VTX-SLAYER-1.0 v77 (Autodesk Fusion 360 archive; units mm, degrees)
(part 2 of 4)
sketch "Skizze49" plane through (0, 0, 7) normal (0, 0, 1) x axis (-1, 0, 0)
  curve K1 (-34.4729, 47.5027) -> (-34.8613, 50.4161)
  line L1 (-32.7992, 19.5622) -> (-34.4732, 21.3854)
  line L2 (21.7601, 20.324) -> (21.0607, 19.5622)
  curve K2 (14.991, 38.4401) -> (21.2218, 28.4813)
  curve K3 (14.991, 41.5582) -> (21.2218, 51.5169)
  line L3 (21.0607, 60.4361) -> (21.7601, 59.6743)
  line L4 (-34.4732, 58.6128) -> (-32.7992, 60.4361)
  line L5 (-23.7522, 44.4991) -> (-30.319, 44.4991)
  line L6 (-30.319, 41.4991) -> (-23.7522, 41.4991)
  line L7 (-23.7522, 38.4991) -> (-30.319, 38.4991)
  line L8 (-30.319, 35.4991) -> (-23.7522, 35.4991)
  curve K4 (-21.4163, 20.9358) -> (-22.7131, 20.0338)
  curve K5 (-21.4163, 59.0625) -> (-22.7131, 59.9644)
  curve K6 (23.3399, 24.4614) -> (21.2218, 28.4813)
  curve K7 (21.2218, 51.5169) -> (23.3399, 55.5369)
  line L9 (-26.3392, 32.4991) -> (-30.319, 32.4991)
  line L10 (-30.319, 29.4991) -> (-26.3392, 29.4991)
  curve K8 (-34.4732, 21.3854) -> (-34.8613, 29.5821)
  curve K9 (-34.8613, 50.4161) -> (-34.4732, 58.6128)
  curve K10 (-34.2161, 44.4991) -> (-34.4729, 47.5027)
  curve K11 (-34.0692, 39.9991) -> (-34.0919, 41.4991)
  curve K12 (-34.0919, 38.4991) -> (-34.0692, 39.9991)
  curve K13 (-34.0919, 38.4991) -> (-34.2161, 35.4991)
  curve K14 (-34.4729, 32.4955) -> (-34.2161, 35.4991)
  line L11 (-26.3392, 50.4991) -> (-30.319, 50.4991)
  line L12 (-30.319, 47.4991) -> (-26.3392, 47.4991)
  curve K15 (-5.8693, 25.0204) -> (1.6863, 24.3869)
  curve K16 (-5.8693, 54.9778) -> (1.6863, 55.6114)
  curve K17 (-32.7992, 19.5622) -> (-25.5215, 18.3445)
  curve K18 (-22.7131, 20.0338) -> (-25.5215, 18.3445)
  curve K19 (-5.8693, 25.0204) -> (-13.4249, 24.3869)
  curve K20 (10.9746, 20.0338) -> (13.7829, 18.3445)
  curve K21 (13.7829, 18.3445) -> (21.0607, 19.5622)
  curve K22 (14.9178, 39.9991) -> (14.991, 38.4401)
  curve K23 (14.9178, 39.9991) -> (14.991, 41.5582)
  curve K24 (13.7829, 61.6537) -> (21.0607, 60.4361)
  curve K25 (10.9746, 59.9644) -> (13.7829, 61.6537)
  curve K26 (-5.8693, 54.9778) -> (-13.4249, 55.6114)
  curve K27 (-22.7131, 59.9644) -> (-25.5215, 61.6537)
  curve K28 (-32.7992, 60.4361) -> (-25.5215, 61.6537)
  curve K29 (-34.0919, 41.4991) -> (-34.2161, 44.4991)
  curve K30 (-21.2077, 21.0728) -> (-21.4163, 20.9358)
  curve K31 (-13.5094, 24.37) -> (-21.2077, 21.0728)
  curve K32 (-13.4249, 24.3869) -> (-13.5094, 24.37)
  curve K33 (1.6863, 24.3869) -> (1.7709, 24.37)
  curve K34 (9.4692, 21.0728) -> (1.7709, 24.37)
  curve K35 (9.4692, 21.0728) -> (9.6778, 20.9358)
  curve K36 (9.6778, 20.9358) -> (10.9746, 20.0338)
  curve K37 (9.6778, 59.0625) -> (10.9746, 59.9644)
  curve K38 (9.4692, 58.9255) -> (9.6778, 59.0625)
  curve K39 (1.7709, 55.6283) -> (9.4692, 58.9255)
  curve K40 (1.6863, 55.6114) -> (1.7709, 55.6283)
  curve K41 (-13.4249, 55.6114) -> (-13.5094, 55.6283)
  curve K42 (-21.2077, 58.9255) -> (-13.5094, 55.6283)
  curve K43 (-21.2077, 58.9255) -> (-21.4163, 59.0625)
  curve K44 (-34.4729, 32.4955) -> (-34.8613, 29.5821)
  circle C1 centre (4.1749, 29.9966) radius 1.05
  circle C2 centre (-15.8251, 49.9966) radius 1.05
  circle C3 centre (-15.8251, 29.9966) radius 1.05
  circle C4 centre (4.1749, 49.9966) radius 1.05
  circle C5 centre (18.1718, 23.4983) radius 2
  circle C6 centre (-29.8282, 23.4983) radius 2
  circle C7 centre (18.1718, 56.4983) radius 2
  circle C8 centre (-29.8282, 56.4983) radius 2
  circle C9 centre (-15.8251, 49.9966) radius 2.1
  circle C10 centre (-15.8251, 29.9966) radius 2.1
  circle C11 centre (4.1749, 29.9966) radius 2.1
  circle C12 centre (4.1749, 49.9966) radius 2.1
  circle C13 centre (-5.8313, 39.9999) radius 2.625
  circle C14 centre (-15.8251, 49.9966) radius 1.05
  circle C15 centre (-15.8251, 29.9966) radius 1.05
  circle C16 centre (4.1749, 49.9966) radius 1.05
  circle C17 centre (4.1749, 29.9966) radius 1.05
  circle C18 centre (-15.8282, 29.9983) radius 2.1
  circle C19 centre (-15.8282, 49.9983) radius 2.1
  circle C20 centre (4.1718, 29.9983) radius 2.1
  circle C21 centre (-5.8282, 39.9983) radius 3
  circle C22 centre (4.1718, 49.9983) radius 2.1
  arc A1 centre (-23.7522, 42.9991) radius 1.5 clockwise from (-23.7522, 44.4991) to (-23.7522, 41.4991)
  arc A2 centre (-30.319, 42.9991) radius 1.5 clockwise from (-30.319, 41.4991) to (-30.319, 44.4991)
  arc A3 centre (-30.319, 36.9991) radius 1.5 clockwise from (-30.319, 35.4991) to (-30.319, 38.4991)
  arc A4 centre (-23.7522, 36.9991) radius 1.5 clockwise from (-23.7522, 38.4991) to (-23.7522, 35.4991)
  arc A5 centre (17.3404, 24.3819) radius 6 clockwise from (23.3399, 24.4614) to (21.7601, 20.324)
  arc A6 centre (17.3404, 55.6164) radius 6 clockwise from (21.7601, 59.6743) to (23.3399, 55.5369)
  arc A7 centre (-26.3392, 30.9991) radius 1.5 clockwise from (-26.3392, 32.4991) to (-26.3392, 29.4991)
  arc A8 centre (-30.319, 30.9991) radius 1.5 clockwise from (-30.319, 29.4991) to (-30.319, 32.4991)
  arc A9 centre (-30.319, 48.9991) radius 1.5 clockwise from (-30.319, 47.4991) to (-30.319, 50.4991)
  arc A10 centre (-26.3392, 48.9991) radius 1.5 clockwise from (-26.3392, 50.4991) to (-26.3392, 47.4991)
  circle C23 centre (-29.8693, 56.4991) radius 2.55
  circle C24 centre (18.1307, 56.4991) radius 2.55
  circle C25 centre (-29.8693, 23.4991) radius 2.55
  circle C26 centre (18.1307, 23.4991) radius 2.55
  circle C27 centre (-5.8693, 39.9991) radius 2.55
  circle C28 centre (-15.8693, 49.9991) radius 1.05
  circle C29 centre (4.1307, 49.9991) radius 1.05
  circle C30 centre (-15.8693, 29.9991) radius 1.05
  circle C31 centre (4.1307, 29.9991) radius 1.05
  dimension "d443" diameter C5 = 4
  dimension "d444" diameter C6 = 4 (= "d443")
  dimension "d445" diameter C7 = 4 (= "d443")
  dimension "d446" diameter C8 = 4 (= "d443")
work_plane "WorkPlane5" AlongDistance 25
sketch "Skizze50" plane through (0, 0, 32) normal (0, 0, 1) x axis (-1, 0, 0)
  line L1 (-34.2161, 35.4991) -> (-33.5931, 35.4991)
  line L2 (-34.2172, 44.4991) -> (-33.5931, 44.4991)
  line L3 (-26.4943, 39.9991) -> (14.9178, 39.9991)
  line L4 (34.1307, 43.8641) -> (34.1307, 36.1341)
  line L5 (21.0607, 19.5622) -> (32.5504, 32.0762)
  line L6 (-32.7992, 19.5622) -> (-33.4986, 20.324)
  line L7 (32.5504, 32.0762) -> (21.0607, 19.5622)
  line L8 (34.1307, 43.8641) -> (34.1307, 36.1341)
  line L9 (21.0607, 60.4361) -> (32.5504, 47.922)
  line L10 (-33.4986, 59.6743) -> (-32.7992, 60.4361)
  curve K1 (-34.4729, 47.5027) -> (-34.8613, 50.4161)
  line L11 (-32.7992, 19.5622) -> (-34.4732, 21.3854)
  line L12 (21.7601, 20.324) -> (21.0607, 19.5622)
  line L13 (21.0607, 60.4361) -> (21.7601, 59.6743)
  line L14 (-34.4732, 58.6128) -> (-32.7992, 60.4361)
  curve K2 (9.6778, 20.9358) -> (10.9746, 20.0338)
  curve K3 (9.6778, 59.0625) -> (10.9746, 59.9644)
  curve K4 (-21.4163, 20.9358) -> (-22.7131, 20.0338)
  curve K5 (-21.4163, 59.0625) -> (-22.7131, 59.9644)
  curve K6 (-35.0785, 55.5369) -> (-32.9603, 51.5169)
  curve K7 (-32.9603, 28.4813) -> (-35.0785, 24.4614)
  curve K8 (23.3399, 24.4614) -> (21.2218, 28.4813)
  curve K9 (21.2218, 51.5169) -> (23.3399, 55.5369)
  line L15 (-26.3392, 32.4991) -> (-30.319, 32.4991)
  line L16 (-30.319, 29.4991) -> (-26.3392, 29.4991)
  curve K10 (-34.4732, 21.3854) -> (-34.8613, 29.5821)
  curve K11 (-34.8613, 50.4161) -> (-34.4732, 58.6128)
  curve K12 (-34.2161, 44.4991) -> (-34.4729, 47.5027)
  curve K13 (-34.0919, 41.4991) -> (-34.2161, 44.4991)
  curve K14 (-34.0692, 39.9991) -> (-34.0919, 41.4991)
  curve K15 (-34.0919, 38.4991) -> (-34.0692, 39.9991)
  curve K16 (-34.0919, 38.4991) -> (-34.2161, 35.4991)
  curve K17 (-34.4729, 32.4955) -> (-34.2161, 35.4991)
  line L17 (-26.3392, 50.4991) -> (-30.319, 50.4991)
  line L18 (-30.319, 47.4991) -> (-26.3392, 47.4991)
  curve K18 (-5.8693, 54.9778) -> (1.6863, 55.6114)
  curve K19 (-5.8693, 54.9778) -> (-13.4249, 55.6114)
  curve K20 (-5.8693, 25.0204) -> (-13.4249, 24.3869)
  curve K21 (-5.8693, 25.0204) -> (1.6863, 24.3869)
  curve K22 (-5.8693, 25.0204) -> (1.6863, 24.3869)
  curve K23 (-5.8693, 54.9778) -> (1.6863, 55.6114)
  curve K24 (-25.5215, 18.3445) -> (-32.7992, 19.5622)
  curve K25 (-22.7131, 20.0338) -> (-25.5215, 18.3445)
  curve K26 (10.9746, 20.0338) -> (13.7829, 18.3445)
  curve K27 (21.0607, 19.5622) -> (13.7829, 18.3445)
  curve K28 (21.0607, 60.4361) -> (13.7829, 61.6537)
  curve K29 (10.9746, 59.9644) -> (13.7829, 61.6537)
  curve K30 (-22.7131, 59.9644) -> (-25.5215, 61.6537)
  curve K31 (-25.5215, 61.6537) -> (-32.7992, 60.4361)
  curve K32 (-32.7992, 19.5622) -> (-25.5215, 18.3445)
  curve K33 (-22.7131, 20.0338) -> (-25.5215, 18.3445)
  curve K34 (-5.8693, 25.0204) -> (-13.4249, 24.3869)
  curve K35 (10.9746, 20.0338) -> (13.7829, 18.3445)
  curve K36 (13.7829, 18.3445) -> (21.0607, 19.5622)
  curve K37 (13.7829, 61.6537) -> (21.0607, 60.4361)
  curve K38 (10.9746, 59.9644) -> (13.7829, 61.6537)
  curve K39 (-5.8693, 54.9778) -> (-13.4249, 55.6114)
  curve K40 (-22.7131, 59.9644) -> (-25.5215, 61.6537)
  curve K41 (-32.7992, 60.4361) -> (-25.5215, 61.6537)
  curve K42 (-21.4163, 20.9358) -> (-22.7131, 20.0338)
  curve K43 (-13.5094, 24.37) -> (-21.4163, 20.9358)
  curve K44 (-13.4249, 24.3869) -> (-13.5094, 24.37)
  curve K45 (1.6863, 24.3869) -> (1.7709, 24.37)
  curve K46 (1.7709, 24.37) -> (9.6778, 20.9358)
  curve K47 (1.7709, 55.6283) -> (9.6778, 59.0625)
  curve K48 (1.6863, 55.6114) -> (1.7709, 55.6283)
  curve K49 (-13.4249, 55.6114) -> (-13.5094, 55.6283)
  curve K50 (-13.5094, 55.6283) -> (-21.4163, 59.0625)
  curve K51 (-21.4163, 59.0625) -> (-22.7131, 59.9644)
  curve K52 (-21.2077, 21.0728) -> (-21.4163, 20.9358)
  curve K53 (-13.5094, 24.37) -> (-21.2077, 21.0728)
  curve K54 (-13.4249, 24.3869) -> (-13.5094, 24.37)
  curve K55 (1.6863, 24.3869) -> (1.7709, 24.37)
  curve K56 (9.4692, 21.0728) -> (1.7709, 24.37)
  curve K57 (9.4692, 21.0728) -> (9.6778, 20.9358)
  curve K58 (9.6778, 20.9358) -> (10.9746, 20.0338)
  curve K59 (9.6778, 59.0625) -> (10.9746, 59.9644)
  curve K60 (9.4692, 58.9255) -> (9.6778, 59.0625)
  curve K61 (1.7709, 55.6283) -> (9.4692, 58.9255)
  curve K62 (1.6863, 55.6114) -> (1.7709, 55.6283)
  curve K63 (-13.4249, 55.6114) -> (-13.5094, 55.6283)
  curve K64 (-21.2077, 58.9255) -> (-13.5094, 55.6283)
  curve K65 (-21.2077, 58.9255) -> (-21.4163, 59.0625)
  curve K66 (-34.4729, 32.4955) -> (-34.8613, 29.5821)
  line L19 (3.2014, 37.2064) -> (18.1307, 23.4991)
  line L20 (3.2014, 42.7918) -> (18.1307, 56.4991)
  line L21 (25.9, 31.9611) -> (18.1307, 23.4991)
  line L22 (25.9, 48.0372) -> (18.1307, 56.4991)
  line L23 (6.5519, 27.8311) -> (12.5889, 23.7993)
  line L24 (6.5519, 52.1671) -> (12.5889, 56.1989)
  line L25 (-12.7701, 29.0204) -> (1.0316, 29.0204)
  line L26 (-12.7701, 50.9778) -> (1.0316, 50.9778)
  line L27 (19.9777, 28.7328) -> (21.5825, 30.4807)
  line L28 (19.9777, 51.2654) -> (21.5825, 49.5175)
  line L29 (-26.1937, 36.9643) -> (-19.1192, 29.9733)
  line L30 (-26.1937, 39.9991) -> (-26.1937, 36.9643)
  line L31 (-26.1937, 43.034) -> (-19.1192, 50.025)
  line L32 (-26.1937, 39.9991) -> (-26.1937, 43.034)
  line L33 (39.4861, -5.3562) -> (4.1307, 29.9991)
  line L34 (54.1307, 29.9991) -> (4.1307, 29.9991)
  line L35 (-51.2246, -5.3562) -> (-15.8693, 29.9991)
  line L36 (34.1307, 29.9991) -> (-15.8693, 29.9991)
  line L37 (-5.7883, 39.9991) -> (4.1307, 29.9991)
  line L38 (-5.7883, 39.9991) -> (-15.8693, 29.9991)
  line L39 (39.4861, 85.3545) -> (4.1307, 49.9991)
  line L40 (-5.7883, 39.9991) -> (4.1307, 49.9991)
  line L41 (-5.7883, 39.9991) -> (-15.8693, 49.9991)
  line L42 (-51.2246, 85.3545) -> (-15.8693, 49.9991)
  line L43 (-2.5295, 39.9991) -> (4.166, 33.2489)
  line L44 (0.9769, 30.784) -> (-5.7883, 37.6045)
  line L45 (-13.4558, 29.9991) -> (-5.7883, 37.6045)
  line L46 (-15.8592, 33.2491) -> (-9.0541, 39.9991)
  line L47 (0.9769, 49.2142) -> (-5.7883, 42.3937)
  line L48 (-2.5295, 39.9991) -> (4.166, 46.7493)
  line L49 (-13.4558, 49.9991) -> (-5.7883, 42.3937)
  line L50 (-15.8592, 46.7491) -> (-9.0541, 39.9991)
  line L51 (14.9457, 39.9991) -> (6.7725, 31.8921)
  line L52 (7.6315, 27.1101) -> (18.0788, 37.4728)
  line L53 (7.6315, 52.8881) -> (18.0788, 42.5254)
  line L54 (14.9457, 39.9991) -> (6.7725, 48.1061)
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  point P2 (-33.5931, 39.9991)
  point P7 (-26.4943, 39.9991)
  point P94 (-34.2161, 35.4991)
  point P141 (-34.2161, 35.4991)
  point P56 (18.1307, 23.4991)
  point P142 (18.1307, 23.4991)
  point P144 (18.1307, 56.4991)
  point P143 (3.2014, 37.2064)
  point P145 (3.2014, 42.7918)
  point P147 (18.1307, 56.4991)
  point P146 (25.9, 31.9611)
  point P148 (25.9, 48.0372)
  point P6 (14.9178, 39.9991)
  point P39 (31.849, 39.9991)
  point P150 (18.1307, 23.4991)
  point P156 (12.5889, 23.7993)
  point P158 (12.5889, 56.1989)
  point P157 (6.5519, 27.8311)
  point P159 (6.5519, 52.1671)
  point P160 (1.0316, 29.0204)
  point P162 (1.0316, 50.9778)
  point P161 (-12.7701, 29.0204)
  point P163 (-12.7701, 50.9778)
  point P164 (21.5825, 30.4807)
  point P166 (21.5825, 49.5175)
  point P165 (19.9777, 28.7328)
  point P167 (19.9777, 51.2654)
  point P170 (-26.1937, 39.9991)
  point P168 (-19.1192, 29.9733)
  point P171 (-19.1192, 50.025)
  point P169 (-26.1937, 36.9643)
  point P172 (-26.1937, 43.034)
  point P173 (-26.1937, 39.9991)
  point P106 (4.1307, 29.9991)
  point P174 (4.1307, 29.9991)
  point P72 (-15.8693, 29.9991)
  point P177 (-15.8693, 29.9991)
  point P180 (-5.7883, 39.9991)
  point P181 (-15.8693, 29.9991)
  point P182 (4.1307, 49.9991)
  point P175 (39.4861, -5.3562)
  point P183 (39.4861, 85.3545)
  point P186 (-15.8693, 49.9991)
  point P178 (-51.2246, -5.3562)
  point P187 (-51.2246, 85.3545)
  point P184 (-5.7883, 39.9991)
  point P185 (-15.8693, 49.9991)
  point P189 (-2.5295, 39.9991)
  point P190 (-5.7883, 37.6045)
  point P192 (-13.4558, 29.9991)
  point P193 (-9.0541, 39.9991)
  point P188 (4.166, 33.2489)
  point P197 (4.166, 46.7493)
  point P198 (-2.5295, 39.9991)
  point P195 (-5.7883, 42.3937)
  point P191 (0.9769, 30.784)
  point P196 (0.9769, 49.2142)
  point P199 (-13.4558, 49.9991)
  point P200 (-9.0541, 39.9991)
  point P194 (-15.8592, 33.2491)
  point P201 (-15.8592, 46.7491)
  point P203 (14.9457, 39.9991)
  point P205 (7.6315, 27.1101)
  point P202 (6.7725, 31.8921)
  point P208 (6.7725, 48.1061)
  point P209 (14.9457, 39.9991)
  point P204 (18.0788, 37.4728)
  point P206 (18.0788, 42.5254)
  point P207 (7.6315, 52.8881)
  point P128 (9.4692, 21.0728)
  point P74 (-5.8693, 25.0204)
  horizontal L1
  horizontal L2
  horizontal P2 P7
  coincident P94 P141
  coincident P56 P142
  symmetric L3 P142 P144
  symmetric L3 P143 P145
  perpendicular L19 L21
  parallel L5 L21
  symmetric L3 P142 P147
  symmetric L3 P146 P148
  horizontal P6 P39
  coincident P142 P150
  symmetric L3 P156 P158
  symmetric L3 P157 P159
  horizontal L25
  symmetric L3 P160 P162
  symmetric L3 P161 P163
  parallel L21 L27
  symmetric L3 P164 P166
  symmetric L3 P165 P167
  coincident L3 P170
  perpendicular L3 L30
  symmetric L3 P168 P171
  symmetric L3 P169 P172
  symmetric L3 P170 P173
  horizontal L34
  coincident P106 P174
  horizontal L36
  coincident P72 P177
  midpoint L3 P180
  coincident P72 P181
  symmetric L3 P174 P182
  symmetric L3 P175 P183
  symmetric L3 P177 P186
  symmetric L3 P178 P187
  symmetric L3 P180 P184
  symmetric L3 P181 P185
  coincident L3 P189
  parallel L37 L43
  parallel L37 L44
  vertical P180 P190
  coincident L36 P192
  perpendicular L44 L45
  coincident L3 P193
  parallel L45 L46
  symmetric L3 P188 P197
  symmetric L3 P189 P198
  symmetric L3 P190 P195
  symmetric L3 P191 P196
  symmetric L3 P192 P199
  symmetric L3 P193 P200
  symmetric L3 P194 P201
  coincident L3 P203
  coincident L23 P205
  parallel L51 L52
  perpendicular L37 L51
  symmetric L3 P202 P208
  symmetric L3 P203 P209
  symmetric L3 P204 P206
  symmetric L3 P205 P207
  dimension "d586" diameter = 9
  dimension "d636" diameter = 20
  dimension "d1095" distance = 4
  dimension "d1096" distance = 4
  dimension "d1098" distance = 2.2
  dimension "d1100" distance = 2.2
  dimension "d1101" distance P128 L23 = 4
  dimension "d1103" distance P74 L25 = 4
  dimension "d1104" distance L5 L27 = 7
  dimension "d1105" angle L33 L34 = 45
  dimension "d1106" distance P174 P175 = 50
  dimension "d1107" angle L35 L36 = 135 (= "90 deg + 45 deg")
  dimension "d1108" distance P177 P178 = 50
  dimension "d1111" distance L43 L44 = 4
  dimension "d1112" distance L45 L46 = 4 (= "d1111")
  dimension "d1113" distance L51 L52 = 4
extrude "Extrude78" new body sketch "Skizze50" along normal blind 1.5
fillet "Fillet34" radius 4
fillet "Fillet103" radius 4
fillet "Fillet37" radius 3
fillet "Fillet104" radius 4
fillet "Fillet105" radius 3
fillet "Fillet106" radius 2
fillet "Fillet107" radius 5
sketch "weight-reduction-m-top" plane through (0, 0, 7) normal (0, 0, 1) x axis (-1, 0, 0)
  line L1 (-26.3392, 32.4991) -> (-30.319, 32.4991)
  line L2 (-30.319, 29.4991) -> (-26.3392, 29.4991)
  curve K1 (-34.4729, 32.4955) -> (-34.8613, 29.5821)
  curve K2 (-34.4732, 21.3854) -> (-34.8613, 29.5821)
  line L3 (-32.7992, 19.5622) -> (-34.4732, 21.3854)
  curve K3 (-21.4163, 20.9358) -> (-22.7131, 20.0338)
  line L4 (21.7601, 20.324) -> (21.0607, 19.5622)
  curve K4 (23.3399, 24.4614) -> (21.2218, 28.4813)
  curve K5 (14.991, 38.4401) -> (21.2218, 28.4813)
  curve K6 (14.991, 41.5582) -> (21.2218, 51.5169)
  curve K7 (21.2218, 51.5169) -> (23.3399, 55.5369)
  line L5 (21.0607, 60.4361) -> (21.7601, 59.6743)
  curve K8 (-21.4163, 59.0625) -> (-22.7131, 59.9644)
  line L6 (-34.4732, 58.6128) -> (-32.7992, 60.4361)
  curve K9 (-34.8613, 50.4161) -> (-34.4732, 58.6128)
  curve K10 (-34.4729, 47.5027) -> (-34.8613, 50.4161)
  curve K11 (-34.2161, 44.4991) -> (-34.4729, 47.5027)
  curve K12 (-34.0919, 41.4991) -> (-34.2161, 44.4991)
  curve K13 (-34.0692, 39.9991) -> (-34.0919, 41.4991)
  curve K14 (-34.0919, 38.4991) -> (-34.0692, 39.9991)
  curve K15 (-34.0919, 38.4991) -> (-34.2161, 35.4991)
  curve K16 (-34.4729, 32.4955) -> (-34.2161, 35.4991)
  line L7 (-23.7522, 38.4991) -> (-30.319, 38.4991)
  line L8 (-30.319, 35.4991) -> (-23.7522, 35.4991)
  line L9 (-23.7522, 44.4991) -> (-30.319, 44.4991)
  line L10 (-30.319, 41.4991) -> (-23.7522, 41.4991)
  line L11 (-26.3392, 50.4991) -> (-30.319, 50.4991)
  line L12 (-30.319, 47.4991) -> (-26.3392, 47.4991)
  line L13 (-3, 17) -> (8, 17)
  line L14 (38, 44) -> (38, 33)
  line L15 (-2.454, 39.9991) -> (16.5436, 39.9991)
  line L16 (-5.8693, 35.997) -> (-5.8693, 24.0226)
  curve K17 (11.053, 39.9991) -> (5.0002, 32.3431)
  curve K18 (11.053, 41.4602) -> (11.053, 38.538)
  curve K19 (5.9236, 32.0012) -> (4.0767, 32.6849)
  curve K20 (11.053, 39.9991) -> (5.0002, 47.6552)
  curve K21 (5.9236, 47.997) -> (4.0767, 47.3133)
  curve K22 (11.053, 38.538) -> (11.053, 41.4602)
  curve K23 (-15.8119, 47.4998) -> (-15.9266, 32.4985)
  curve K24 (-16.9524, 32.4749) -> (-14.9008, 32.522)
  curve K25 (-14.7861, 47.5233) -> (-16.8377, 47.4762)
  curve K26 (-5.8693, 30.0098) -> (2.0117, 31.3257)
  curve K27 (1.7635, 30.9291) -> (2.26, 31.7222)
  curve K28 (-7, 30.0098) -> (-4.7385, 30.0098)
  curve K29 (-5.8693, 30.0098) -> (-13.7502, 31.3257)
  curve K30 (-13.502, 30.9291) -> (-13.9985, 31.7222)
  curve K31 (-4.7385, 30.0098) -> (-7, 30.0098)
  curve K32 (-5.8693, 49.9885) -> (-13.7502, 48.6726)
  curve K33 (-13.502, 49.0691) -> (-13.9985, 48.276)
  curve K34 (-4.7385, 49.9885) -> (-7, 49.9885)
  curve K35 (-5.8693, 49.9885) -> (2.0117, 48.6726)
  curve K36 (1.7635, 49.0691) -> (2.26, 48.276)
  curve K37 (-7, 49.9885) -> (-4.7385, 49.9885)
  curve K38 (-5.8693, 25.0204) -> (1.6863, 24.3869)
  curve K39 (-5.8693, 54.9778) -> (1.6863, 55.6114)
  curve K40 (-32.7992, 19.5622) -> (-25.5215, 18.3445)
  curve K41 (-22.7131, 20.0338) -> (-25.5215, 18.3445)
  curve K42 (-5.8693, 25.0204) -> (-13.4249, 24.3869)
  curve K43 (10.9746, 20.0338) -> (13.7829, 18.3445)
  curve K44 (13.7829, 18.3445) -> (21.0607, 19.5622)
  curve K45 (14.9178, 39.9991) -> (14.991, 38.4401)
  curve K46 (14.9178, 39.9991) -> (14.991, 41.5582)
  curve K47 (13.7829, 61.6537) -> (21.0607, 60.4361)
  curve K48 (10.9746, 59.9644) -> (13.7829, 61.6537)
  curve K49 (-5.8693, 54.9778) -> (-13.4249, 55.6114)
  curve K50 (-22.7131, 59.9644) -> (-25.5215, 61.6537)
  curve K51 (-32.7992, 60.4361) -> (-25.5215, 61.6537)
  curve K52 (-21.2077, 21.0728) -> (-21.4163, 20.9358)
  curve K53 (-13.5094, 24.37) -> (-21.2077, 21.0728)
  curve K54 (-13.4249, 24.3869) -> (-13.5094, 24.37)
  curve K55 (1.6863, 24.3869) -> (1.7709, 24.37)
  curve K56 (9.4692, 21.0728) -> (1.7709, 24.37)
  curve K57 (9.4692, 21.0728) -> (9.6778, 20.9358)
  curve K58 (9.6778, 20.9358) -> (10.9746, 20.0338)
  curve K59 (9.6778, 59.0625) -> (10.9746, 59.9644)
  curve K60 (9.4692, 58.9255) -> (9.6778, 59.0625)
  curve K61 (1.7709, 55.6283) -> (9.4692, 58.9255)
  curve K62 (1.6863, 55.6114) -> (1.7709, 55.6283)
  curve K63 (-13.4249, 55.6114) -> (-13.5094, 55.6283)
  curve K64 (-21.2077, 58.9255) -> (-13.5094, 55.6283)
  curve K65 (-21.2077, 58.9255) -> (-21.4163, 59.0625)
  arc A1 centre (-26.3392, 30.9991) radius 1.5 clockwise from (-26.3392, 32.4991) to (-26.3392, 29.4991)
  arc A2 centre (-30.319, 30.9991) radius 1.5 clockwise from (-30.319, 29.4991) to (-30.319, 32.4991)
  arc A3 centre (17.3404, 24.3819) radius 6 clockwise from (23.3399, 24.4614) to (21.7601, 20.324)
  arc A4 centre (17.3404, 55.6164) radius 6 clockwise from (21.7601, 59.6743) to (23.3399, 55.5369)
  arc A5 centre (-23.7522, 36.9991) radius 1.5 clockwise from (-23.7522, 38.4991) to (-23.7522, 35.4991)
  arc A6 centre (-30.319, 36.9991) radius 1.5 clockwise from (-30.319, 35.4991) to (-30.319, 38.4991)
  arc A7 centre (-30.319, 42.9991) radius 1.5 clockwise from (-30.319, 41.4991) to (-30.319, 44.4991)
  arc A8 centre (-23.7522, 42.9991) radius 1.5 clockwise from (-23.7522, 44.4991) to (-23.7522, 41.4991)
  arc A9 centre (-30.319, 48.9991) radius 1.5 clockwise from (-30.319, 47.4991) to (-30.319, 50.4991)
  arc A10 centre (-26.3392, 48.9991) radius 1.5 clockwise from (-26.3392, 50.4991) to (-26.3392, 47.4991)
  circle C1 centre (-29.8693, 56.4991) radius 2.55
  circle C2 centre (18.1307, 56.4991) radius 2.55
  circle C3 centre (-29.8693, 23.4991) radius 2.55
  circle C4 centre (18.1307, 23.4991) radius 2.55
  circle C5 centre (4.1307, 29.9991) radius 2.5
  circle C6 centre (-15.8693, 29.9991) radius 2.5
  circle C7 centre (4.1307, 49.9991) radius 2.5
  circle C8 centre (-15.8693, 49.9991) radius 2.5
  circle C9 centre (-5.8693, 39.9991) radius 2.55
  circle C10 centre (-15.8693, 49.9991) radius 1.05
  circle C11 centre (4.1307, 49.9991) radius 1.05
  circle C12 centre (-15.8693, 29.9991) radius 1.05
  circle C13 centre (4.1307, 29.9991) radius 1.05
  point P70 (11.053, 39.9991)
  point P73 (5.0002, 32.3431)
  point P77 (11.053, 39.9991)
  point P71 (11.053, 38.538)
  point P80 (11.053, 41.4602)
  point P72 (11.053, 41.4602)
  point P81 (11.053, 38.538)
  point P76 (5.0002, 47.6552)
  point P74 (4.0767, 32.6849)
  point P78 (4.0767, 47.3133)
  point P75 (5.9236, 32.0012)
  point P79 (5.9236, 47.997)
  point P82 (-15.9266, 32.4985)
  point P83 (-15.8119, 47.4998)
  point P88 (2.0117, 31.3257)
  point P89 (-5.8693, 30.0098)
  point P94 (-13.7502, 31.3257)
  point P95 (-5.8693, 30.0098)
  point P90 (2.26, 31.7222)
  point P96 (-13.9985, 31.7222)
  point P91 (1.7635, 30.9291)
  point P97 (-13.502, 30.9291)
  point P92 (-4.7385, 30.0098)
  point P98 (-7, 30.0098)
  point P93 (-7, 30.0098)
  point P99 (-4.7385, 30.0098)
  point P106 (2.0117, 48.6726)
  point P107 (-5.8693, 49.9885)
  point P108 (2.26, 48.276)
  point P109 (1.7635, 49.0691)
  point P110 (-4.7385, 49.9885)
  point P111 (-7, 49.9885)
  point P100 (-13.7502, 48.6726)
  point P101 (-5.8693, 49.9885)
  point P102 (-13.9985, 48.276)
  point P103 (-13.502, 49.0691)
  point P104 (-7, 49.9885)
  point P105 (-4.7385, 49.9885)
  horizontal L13
  perpendicular L13 L14
  coincident L15 P70
  midpoint P70 K18
  coincident C5 P73
  midpoint P73 K19
  tangent C5 K19
  parallel L14 K18
  symmetric L15 P70 P77
  symmetric L15 P71 P80
  symmetric L15 P72 P81
  symmetric L15 P73 P76
  symmetric L15 P74 P78
  symmetric L15 P75 P79
  coincident C6 P82
  coincident C8 P83
  midpoint P82 K24
  tangent C6 K24
  midpoint P83 K25
  tangent C8 K25
  parallel K24 K25
  equal K24 K25
  coincident C5 P88
  midpoint L16 P89
  midpoint P88 K27
  tangent C5 K27
  midpoint P89 K28
  parallel L15 K28
  symmetric L16 P88 P94
  symmetric L16 P89 P95
  symmetric L16 P90 P96
  symmetric L16 P91 P97
  symmetric L16 P92 P98
  symmetric L16 P93 P99
  symmetric L15 P88 P106
  symmetric L15 P89 P107
  symmetric L15 P90 P108
  symmetric L15 P91 P109
  symmetric L15 P92 P110
  symmetric L15 P93 P111
  symmetric L15 P94 P100
  symmetric L15 P95 P101
  symmetric L15 P96 P102
  symmetric L15 P97 P103
  symmetric L15 P98 P104
  symmetric L15 P99 P105
  dimension "d692" diameter C5 = 5
  dimension "d693" diameter C6 = 5
  dimension "d694" diameter C7 = 5
  dimension "d695" diameter C8 = 5
extrude "Extrude85" cut sketch "weight-reduction-m-top" profile of C5 C6 C7 C8 K17 K20 K23 K26 K29 K32 K35 against normal blind 2
sketch "weight-reduction-m-center" plane through (0, 0, 5) normal (0, 0, 1) x axis (-1, 0, 0)
  curve K1 (-26.6974, 39.9991) -> (-25.0329, 29.8104)
  curve K2 (-24.8323, 29.8846) -> (-25.0329, 29.8104)
  curve K3 (-22.3693, 34.4991) -> (-24.8323, 29.8846)
  line L1 (-19.3693, 25.3947) -> (-19.3693, 34.4991)
  curve K4 (-17.2278, 23.275) -> (-19.3693, 25.3947)
  curve K5 (5.4893, 23.275) -> (7.6307, 25.3947)
  line L2 (7.6307, 34.4991) -> (7.6307, 25.3947)
  curve K6 (10.6307, 34.4991) -> (13.0937, 29.8846)
  curve K7 (13.0937, 29.8846) -> (13.2943, 29.8104)
  curve K8 (14.9589, 39.9991) -> (13.2943, 29.8104)
  curve K9 (14.9589, 39.9991) -> (13.2943, 50.1878)
  curve K10 (13.0937, 50.1137) -> (13.2943, 50.1878)
  curve K11 (10.6307, 45.4991) -> (13.0937, 50.1137)
  line L3 (7.6307, 54.6035) -> (7.6307, 45.4991)
  curve K12 (5.4893, 56.7233) -> (7.6307, 54.6035)
  curve K13 (-17.2278, 56.7233) -> (-19.3693, 54.6035)
  line L4 (-19.3693, 45.4991) -> (-19.3693, 54.6035)
  curve K14 (-22.3693, 45.4991) -> (-24.8323, 50.1137)
  curve K15 (-24.8323, 50.1137) -> (-25.0329, 50.1878)
  curve K16 (-26.6974, 39.9991) -> (-25.0329, 50.1878)
  curve K17 (-5.8693, 25.0204) -> (-17.2278, 23.275)
  curve K18 (-5.8693, 25.0204) -> (5.4893, 23.275)
  curve K19 (-5.8693, 54.9778) -> (5.4893, 56.7233)
  curve K20 (-5.8693, 54.9778) -> (-17.2278, 56.7233)
  arc A1 centre (-20.8693, 34.4991) radius 1.5 clockwise from (-22.3693, 34.4991) to (-19.3693, 34.4991)
  arc A2 centre (9.1307, 34.4991) radius 1.5 clockwise from (7.6307, 34.4991) to (10.6307, 34.4991)
  arc A3 centre (9.1307, 45.4991) radius 1.5 clockwise from (10.6307, 45.4991) to (7.6307, 45.4991)
  arc A4 centre (-20.8693, 45.4991) radius 1.5 clockwise from (-19.3693, 45.4991) to (-22.3693, 45.4991)
  circle C1 centre (4.1307, 49.9991) radius 2.1
  circle C2 centre (-15.8693, 49.9991) radius 2.1
  circle C3 centre (-15.8693, 29.9991) radius 2.1
  circle C4 centre (4.1307, 29.9991) radius 2.1
  circle C5 centre (-5.8693, 39.9991) radius 1.55
  circle C6 centre (-5.8693, 39.9991) radius 8.75
  circle C7 centre (4.1307, 29.9991) radius 1.05
  circle C8 centre (-15.8693, 29.9991) radius 1.05
  circle C9 centre (4.1307, 49.9991) radius 1.05
  circle C10 centre (-15.8693, 49.9991) radius 1.05
  concentric C5 C6
  concentric C4 C7
  concentric C3 C8
  concentric C1 C9
  concentric C2 C10
  dimension "d700" diameter C6 = 17.5
  dimension "d703" diameter C7 = 2.1
  dimension "d704" diameter C8 = 2.1 (= "d703")
  dimension "d705" diameter C9 = 2.1 (= "d703")
  dimension "d706" diameter C10 = 2.1 (= "d703")
extrude "Extrude86" cut sketch "weight-reduction-m-center" profile of C5 C6 against normal blind 2
extrude "Extrude87" add sketch "weight-reduction-m-center" profile of C1 C2 C3 C4 C7 C8 C9 C10 against normal blind 2
component_insert "Component Insert4"
sketch "cam-mount-base" plane through (0, 0, 7) normal (0, 0, 1) x axis (-1, 0, 0)
  curve K1 (2.0117, 48.6726) -> (-5.8693, 49.9885)
  curve K2 (11.053, 39.9991) -> (5.0002, 47.6552)
  curve K3 (5.0002, 32.3431) -> (11.053, 39.9991)
  curve K4 (-5.8693, 30.0098) -> (2.0117, 31.3257)
  curve K5 (-13.7502, 31.3257) -> (-5.8693, 30.0098)
  curve K6 (-15.8119, 47.4998) -> (-15.9266, 32.4985)
  curve K7 (-5.8693, 49.9885) -> (-13.7502, 48.6726)
  line L1 (-26.3392, 32.4991) -> (-30.319, 32.4991)
  line L2 (-30.319, 29.4991) -> (-26.3392, 29.4991)
  curve K8 (-34.4729, 32.4955) -> (-34.8613, 29.5821)
  curve K9 (-34.4732, 21.3854) -> (-34.8613, 29.5821)
  line L3 (-32.7992, 19.5622) -> (-34.4732, 21.3854)
  curve K10 (-21.4163, 20.9358) -> (-22.7131, 20.0338)
  line L4 (21.7601, 20.324) -> (21.0607, 19.5622)
  curve K11 (23.3399, 24.4614) -> (21.2218, 28.4813)
  curve K12 (14.991, 38.4401) -> (21.2218, 28.4813)
  curve K13 (14.991, 41.5582) -> (21.2218, 51.5169)
  curve K14 (21.2218, 51.5169) -> (23.3399, 55.5369)
  line L5 (21.0607, 60.4361) -> (21.7601, 59.6743)
  curve K15 (-21.4163, 59.0625) -> (-22.7131, 59.9644)
  line L6 (-34.4732, 58.6128) -> (-32.7992, 60.4361)
  curve K16 (-34.8613, 50.4161) -> (-34.4732, 58.6128)
  curve K17 (-34.4729, 47.5027) -> (-34.8613, 50.4161)
  curve K18 (-34.2161, 44.4991) -> (-34.4729, 47.5027)
  curve K19 (-34.0919, 41.4991) -> (-34.2161, 44.4991)
  curve K20 (-34.0692, 39.9991) -> (-34.0919, 41.4991)
  curve K21 (-34.0919, 38.4991) -> (-34.0692, 39.9991)
  curve K22 (-34.0919, 38.4991) -> (-34.2161, 35.4991)
  curve K23 (-34.4729, 32.4955) -> (-34.2161, 35.4991)
  line L7 (-23.7522, 38.4991) -> (-30.319, 38.4991)
  line L8 (-30.319, 35.4991) -> (-23.7522, 35.4991)
  line L9 (-23.7522, 44.4991) -> (-30.319, 44.4991)
  line L10 (-30.319, 41.4991) -> (-23.7522, 41.4991)
  line L11 (-26.3392, 50.4991) -> (-30.319, 50.4991)
  line L12 (-30.319, 47.4991) -> (-26.3392, 47.4991)
  line L13 (-2.454, 39.9991) -> (16.5436, 39.9991)
  line L14 (49, 49.9991) -> (7.5, 49.9991)
  line L15 (49, 29.9991) -> (7.5, 29.9991)
  line L16 (32.5785, 49.9991) -> (20.5106, 49.9991)
  line L17 (32.5785, 29.9991) -> (20.5106, 29.9991)
  line L18 (20.5106, 29.9991) -> (20.5106, 49.9991)
  curve K24 (-5.8693, 25.0204) -> (1.6863, 24.3869)
  curve K25 (-5.8693, 54.9778) -> (1.6863, 55.6114)
  curve K26 (-32.7992, 19.5622) -> (-25.5215, 18.3445)
  curve K27 (-22.7131, 20.0338) -> (-25.5215, 18.3445)
  curve K28 (-5.8693, 25.0204) -> (-13.4249, 24.3869)
  curve K29 (10.9746, 20.0338) -> (13.7829, 18.3445)
  curve K30 (13.7829, 18.3445) -> (21.0607, 19.5622)
  curve K31 (14.9178, 39.9991) -> (14.991, 38.4401)
  curve K32 (14.9178, 39.9991) -> (14.991, 41.5582)
  curve K33 (13.7829, 61.6537) -> (21.0607, 60.4361)
  curve K34 (10.9746, 59.9644) -> (13.7829, 61.6537)
  curve K35 (-5.8693, 54.9778) -> (-13.4249, 55.6114)
  curve K36 (-22.7131, 59.9644) -> (-25.5215, 61.6537)
  curve K37 (-32.7992, 60.4361) -> (-25.5215, 61.6537)
  curve K38 (-21.2077, 21.0728) -> (-21.4163, 20.9358)
  curve K39 (-13.5094, 24.37) -> (-21.2077, 21.0728)
  curve K40 (-13.4249, 24.3869) -> (-13.5094, 24.37)
  curve K41 (1.6863, 24.3869) -> (1.7709, 24.37)
  curve K42 (9.4692, 21.0728) -> (1.7709, 24.37)
  curve K43 (9.4692, 21.0728) -> (9.6778, 20.9358)
  curve K44 (9.6778, 20.9358) -> (10.9746, 20.0338)
  curve K45 (9.6778, 59.0625) -> (10.9746, 59.9644)
  curve K46 (9.4692, 58.9255) -> (9.6778, 59.0625)
  curve K47 (1.7709, 55.6283) -> (9.4692, 58.9255)
  curve K48 (1.6863, 55.6114) -> (1.7709, 55.6283)
  curve K49 (-13.4249, 55.6114) -> (-13.5094, 55.6283)
  curve K50 (-21.2077, 58.9255) -> (-13.5094, 55.6283)
  curve K51 (-21.2077, 58.9255) -> (-21.4163, 59.0625)
  arc A1 centre (4.1307, 49.9991) radius 2.5 clockwise from (5.0002, 47.6552) to (2.0117, 48.6726)
  arc A2 centre (4.1307, 29.9991) radius 2.5 clockwise from (2.0117, 31.3257) to (5.0002, 32.3431)
  arc A3 centre (-15.8693, 29.9991) radius 2.5 clockwise from (-15.9266, 32.4985) to (-13.7502, 31.3257)
  arc A4 centre (-15.8693, 49.9991) radius 2.5 clockwise from (-13.7502, 48.6726) to (-15.8119, 47.4998)
  arc A5 centre (-26.3392, 30.9991) radius 1.5 clockwise from (-26.3392, 32.4991) to (-26.3392, 29.4991)
  arc A6 centre (-30.319, 30.9991) radius 1.5 clockwise from (-30.319, 29.4991) to (-30.319, 32.4991)
  arc A7 centre (17.3404, 24.3819) radius 6 clockwise from (23.3399, 24.4614) to (21.7601, 20.324)
  arc A8 centre (17.3404, 55.6164) radius 6 clockwise from (21.7601, 59.6743) to (23.3399, 55.5369)
  arc A9 centre (-23.7522, 36.9991) radius 1.5 clockwise from (-23.7522, 38.4991) to (-23.7522, 35.4991)
  arc A10 centre (-30.319, 36.9991) radius 1.5 clockwise from (-30.319, 35.4991) to (-30.319, 38.4991)
  arc A11 centre (-30.319, 42.9991) radius 1.5 clockwise from (-30.319, 41.4991) to (-30.319, 44.4991)
  arc A12 centre (-23.7522, 42.9991) radius 1.5 clockwise from (-23.7522, 44.4991) to (-23.7522, 41.4991)
  arc A13 centre (-30.319, 48.9991) radius 1.5 clockwise from (-30.319, 47.4991) to (-30.319, 50.4991)
  arc A14 centre (-26.3392, 48.9991) radius 1.5 clockwise from (-26.3392, 50.4991) to (-26.3392, 47.4991)
  circle C1 centre (-29.8693, 56.4991) radius 2.55
  circle C2 centre (18.1307, 56.4991) radius 2.55
  circle C3 centre (-29.8693, 23.4991) radius 2.55
  circle C4 centre (18.1307, 23.4991) radius 2.55
  circle C5 centre (18.1307, 23.4991) radius 3.025
  circle C6 centre (18.1307, 56.4991) radius 3.025
  circle C7 centre (18.1307, 23.4991) radius 5.025
  circle C8 centre (18.1307, 56.4991) radius 5.025
  arc A15 centre (21.2571, 58.9913) radius 9.0231 clockwise from (20.5106, 49.9991) to (14.2014, 53.3668)
  arc A16 centre (21.2571, 21.0069) radius 9.0231 clockwise from (14.2014, 26.6314) to (20.5106, 29.9991)
  arc A17 centre (42.6327, 71.4187) radius 23.6619 clockwise from (32.5785, 49.9991) to (22.4227, 59.1125)
  arc A18 centre (42.6327, 8.5795) radius 23.6619 clockwise from (22.4227, 20.8857) to (32.5785, 29.9991)
  arc A19 centre (24.1325, 39.9991) radius 13.0895 clockwise from (32.5785, 49.9991) to (32.5785, 29.9991)
  circle C9 centre (-15.8693, 49.9991) radius 1.05
  circle C10 centre (4.1307, 49.9991) radius 1.05
  circle C11 centre (-15.8693, 29.9991) radius 1.05
  circle C12 centre (4.1307, 29.9991) radius 1.05
  point P77 (14.2014, 53.3668)
  point P83 (14.2014, 26.6314)
  point P78 (20.5106, 49.9991)
  point P84 (20.5106, 29.9991)
  point P85 (7.5, 49.9991)
  point P87 (7.5, 29.9991)
  point P86 (49, 49.9991)
  point P88 (49, 29.9991)
  point P89 (22.4227, 59.1125)
  point P93 (22.4227, 20.8857)
  point P90 (32.5785, 49.9991)
  point P94 (32.5785, 29.9991)
  point P95 (32.5785, 49.9991)
  point P96 (20.5106, 29.9991)
  point P97 (32.5785, 29.9991)
  concentric C4 C5
  concentric C2 C6
  concentric C4 C7
  concentric C6 C8
  equal C7 C8
  tangent C8 A15
  coincident C8 P77
  symmetric P77 L13 P83
  symmetric P78 L13 P84
  symmetric A15 L13 A16
  horizontal L14
  symmetric L13 P85 P87
  symmetric L13 P86 P88
  coincident P78 L14
  tangent C8 A17
  coincident C8 P89
  symmetric L13 P89 P93
  symmetric L13 P90 P94
  symmetric L13 A17 A18
  coincident L14 P95
  vertical P90 P95
  symmetric P78 L13 P96
  symmetric L13 P95 P97
  coincident L14 P90
  dimension "d713" diameter C5 = 6.05
  dimension "d714" diameter C6 = 6.05 (= "d713")
  dimension "d715" diameter C7 = 10.05 (= "d713 + 4 mm")
  dimension "d716" distance L13 L14 = 10
sketch "Sketch65" plane through (0, -46, 0) normal (0, -1, 0) x axis (1, 0, 0)
  circle C1 centre (-28.7111, 17.4065) radius 0.975
sketch "Sketch66" plane through (0, -34, 0) normal (0, 1, 0) x axis (-1, 0, 0)
  curve K1 (29.1562, 16.539) -> (27.8436, 17.8516)
  arc A1 centre (28.7111, 17.4065) radius 0.975 clockwise from (29.1562, 16.539) to (27.8436, 17.8516)
work_axis "WorkAxis7"
position "Position2"
work_plane "WorkPlane12" AlongDistance 10.5
sketch "motor diams" plane through (0, 0, 5) normal (0, 0, 1) x axis (-1, 0, 0)
  line L1 (45.6984, 88.6696) -> (46.2975, 88.6508)
  line L2 (46.3634, 90.7497) -> (45.7643, 90.7686)
  line L3 (53.0046, 94.732) -> (53.0363, 95.3296)
  line L4 (50.9392, 95.441) -> (50.9075, 94.8433)
  line L5 (57.0019, 88.0092) -> (57.5891, 87.9367)
  line L6 (57.8463, 90.0209) -> (57.259, 90.0934)
  line L7 (42.6895, 76.3401) -> (26.9801, 60.9632)
  curve K1 (42.6895, 76.3401) -> (58.4159, 84.3161)
  curve K2 (52.3801, 102.7764) -> (47.6742, 96.5557)
  curve K3 (43.0511, 92.8338) -> (39.5769, 81.6893)
  line L8 (25.1132, 67.5318) -> (39.5769, 81.6893)
  curve K4 (25.1132, 67.5318) -> (14.076, 61.8127)
  curve K5 (10.9746, 59.9644) -> (9.6778, 59.0625)
  curve K6 (9.6778, 59.0625) -> (7.6307, 54.6035)
  line L9 (7.6307, 45.4991) -> (7.6307, 54.6035)
  curve K7 (10.6307, 45.4991) -> (22.3176, 52.2655)
  curve K8 (22.3176, 52.2655) -> (26.9801, 60.9632)
  curve K9 (65.0703, 88.0717) -> (52.3801, 102.7764)
  curve K10 (47.6742, 96.5557) -> (43.0511, 92.8338)
  curve K11 (58.4159, 84.3161) -> (65.0703, 88.0717)
  curve K12 (14.076, 61.8127) -> (10.9746, 59.9644)
  arc A1 centre (46.3305, 89.7003) radius 1.05 clockwise from (46.3634, 90.7497) to (46.2975, 88.6508)
  arc A2 centre (45.7313, 89.7191) radius 1.05 clockwise from (45.6984, 88.6696) to (45.7643, 90.7686)
  circle C1 centre (18.1307, 56.4991) radius 1.55
  arc A3 centre (51.956, 94.7877) radius 1.05 clockwise from (53.0046, 94.732) to (50.9075, 94.8433)
  arc A4 centre (51.9878, 95.3853) radius 1.05 clockwise from (50.9392, 95.441) to (53.0363, 95.3296)
  circle C2 centre (51.7305, 89.3877) radius 2.7
  arc A5 centre (57.1305, 89.0513) radius 1.05 clockwise from (57.0019, 88.0092) to (57.259, 90.0934)
  arc A6 centre (57.7177, 88.9788) radius 1.05 clockwise from (57.8463, 90.0209) to (57.5891, 87.9367)
  arc A7 centre (9.1307, 45.4991) radius 1.5 clockwise from (10.6307, 45.4991) to (7.6307, 45.4991)
  circle C3 centre (51.7305, -9.3895) radius 2.7
  circle C4 centre (-63.469, -9.3895) radius 2.7
  circle C5 centre (-63.469, 89.3877) radius 2.7
  circle C6 centre (51.7305, -9.3895) radius 38.1
  circle C7 centre (51.7305, 89.3877) radius 38.1
  circle C8 centre (-63.469, -9.3895) radius 38.1
  circle C9 centre (-63.469, 89.3877) radius 38.1
  concentric C3 C6
  concentric C2 C7
  concentric C4 C8
  concentric C5 C9
  dimension "d802" diameter C6 = 76.2 (= "3")
  dimension "d803" diameter C7 = 76.2 (= "3")
  dimension "d804" diameter C8 = 76.2 (= "3")
  dimension "d805" diameter C9 = 76.2 (= "3")
sketch "Sketch67" plane through (0, 0, 17.5) normal (0, 0, 1) x axis (1, 0, 0)
  line L1 (-32.5785, -49.9991) -> (-20.5106, -49.9991)
  line L2 (-32.5785, -29.9991) -> (-20.5106, -29.9991)
  line L3 (-20.5106, -29.9991) -> (-20.5106, -28.2837)
  line L4 (-44.8223, -29.9991) -> (-32.5785, -29.9991)
  line L5 (-44.8223, -49.9991) -> (-44.8223, -29.9991)
  line L6 (-32.5785, -49.9991) -> (-44.8223, -49.9991)
  line L7 (2.454, -39.9991) -> (-16.5436, -39.9991)
  line L8 (-20.5106, -49.9991) -> (-20.5106, -51.7145)
  line L9 (-28.8223, -49.9991) -> (-28.8223, -29.9991)
  point P4 (-20.5106, -29.9991)
  point P7 (-20.5106, -29.9991)
  point P5 (-32.5785, -29.9991)
  point P8 (-32.5785, -29.9991)
  point P3 (-32.5785, -49.9991)
  point P11 (-32.5785, -49.9991)
  point P6 (-20.5106, -28.2837)
  point P14 (-20.5106, -51.7145)
  point P15 (-20.5106, -49.9991)
  point P16 (-28.8223, -29.9991)
  point P17 (-28.8223, -49.9991)
  coincident P4 P7
  perpendicular L2 L3
  coincident P5 P8
  parallel L2 L4
  perpendicular L4 L5
  coincident P3 P11
  symmetric P6 L7 P14
  symmetric P7 L7 P15
  coincident L2 P16
  coincident L1 P17
  perpendicular L1 L9
  parallel L4 L6
  dimension "d844" distance L5 L9 = 16
revolve "Revolve1" sketch "Sketch67" AlongAngle 90 AgainstAngle 90
sketch "Sketch75" plane through (0, -49.9991, 0) normal (0, -1, 0) x axis (1, 0, 0)
  line L1 (-28.8223, 29.4065) -> (-28.8223, 17.4065)
  line L2 (-28.8223, 1.4065) -> (-28.8223, 17.4065)
  line L3 (-28.8223, 33.5) -> (-28.8223, 21.2561)
  line L4 (-28.8223, 17.5) -> (-28.8223, 13.7439)
  arc A1 centre (-28.8223, 17.5) radius 16 clockwise from (-28.8223, 1.5) to (-28.8223, 33.5)
  arc A2 centre (-23.7386, 15.4065) radius 14.8944 clockwise from (-28.8223, 1.4065) to (-28.8223, 29.4065)
  point P6 (-28.8223, 17.4065)
  point P8 (-28.8223, 17.4065)
  point P5 (-28.7111, 17.4065)
  point P7 (-28.8223, 29.4065)
  point P9 (-28.8223, 1.4065)
  coincident P6 P8
  horizontal P5 P8
  dimension "d808" distance P6 P7 = 12
  dimension "d809" distance P8 P9 = 16
sketch "Sketch76" plane through (0, -29.9991, 0) normal (0, 1, 0) x axis (-1, 0, 0)
  line L1 (28.8223, 1.5) -> (28.8223, 33.5)
  line L2 (28.8223, 29.4065) -> (28.8223, 17.4065)
  line L3 (28.8223, 1.4065) -> (28.8223, 17.4065)
  arc A1 centre (28.8223, 17.5) radius 16 clockwise from (28.8223, 33.5) to (28.8223, 1.5)
  arc A2 centre (23.7386, 15.4065) radius 14.8944 clockwise from (28.8223, 29.4065) to (28.8223, 1.4065)
extrude "Extrude101" add sketch "Sketch75" profile of L1 L2 A2 along normal blind 2
extrude "Extrude102" add sketch "Sketch76" along normal blind 2
extrude "Extrude89" add sketch "cam-mount-base" profile of L4 A7 K11 K12 K13 K14 A8 L5 K28 C5 C6 C7 C8 A15 A16 A17 A18 L16 L17 along normal blind 25
extrude "Extrude93" add sketch "cam-mount-base" profile of L4 A7 K11 K12 K13 K14 A8 L5 K28 C5 C6 C7 C8 A15 A16 A17 A18 L16 L17 against normal blind 7
sketch "Sketch80" plane through (0, -49.9991, 0) normal (0, 1, 0) x axis (-1, 0, 0)
  line L1 (28.8223, 32) -> (28.8223, 1.5)
  line L2 (20.5106, 32) -> (28.8223, 32)
  line L3 (20.5106, 0) -> (20.5106, 32)
  line L4 (32.5785, 0) -> (20.5106, 0)
  line L5 (32.5785, 1.9471) -> (32.5785, 0)
  line L6 (13.1, 0) -> (32.5785, 0)
  line L7 (13.1, 2.5) -> (13.1, 0)
  line L8 (32.5785, 2.5) -> (13.1, 2.5)
  line L9 (32.5785, 0) -> (32.5785, 2.5)
  arc A1 centre (28.8223, 17.5) radius 16 clockwise from (32.5785, 1.9471) to (28.8223, 1.5)
  point P8 (32.5785, 0)
  point P9 (32.5785, 0)
  horizontal L6
  vertical L7
  horizontal L8
  vertical L9
  coincident P8 P9
extrude "Extrude106" add sketch "Sketch80" profile of A1 L1 L3 L4 L5 L6 L8 L9 along normal blind 20
sketch "Sketch68" plane through (5.8693, -30.0098, 0) normal (1, 0, 0) x axis (0, 1, 0)
  line L1 (-37, 7) -> (21, 7)
  line L2 (-37, -10) -> (-37, 7)
  line L3 (21, -10) -> (-37, -10)
  line L4 (21, 7) -> (21, -10)
  line L5 (-37, 5) -> (21, 5)
  line L6 (17, 47) -> (-34, 47)
  line L7 (17, 32) -> (17, 47)
  line L8 (-34, 32) -> (17, 32)
  line L9 (-34, 47) -> (-34, 32)
  line L10 (-2.1, 21) -> (-17.9, 21)
  line L11 (-2.1, 44.5) -> (-2.1, 21)
  line L12 (-17.9, 44.5) -> (-2.1, 44.5)
  line L13 (-17.9, 21) -> (-17.9, 44.5)
  line L14 (-37, 0) -> (21, 0)
  circle C1 centre (-10, 21) radius 7.9
  point P6 (21, 5)
  point P7 (-37, 5)
  point P13 (-17.9, 21)
  point P14 (-2.1, 21)
  point P17 (21, 0)
  horizontal L1
  vertical L2
  horizontal L3
  vertical L4
  coincident L4 P6
  coincident L2 P7
  perpendicular L2 L5
  horizontal L6
  vertical L7
  horizontal L8
  vertical L9
  horizontal L10
  vertical L11
  horizontal L12
  vertical L13
  coincident C1 P13
  coincident C1 P14
  coincident L4 P17
  perpendicular L4 L14
  dimension "d745" diameter C1 = 15.8
  dimension "d778" distance L1 L14 = 7
shell "Shell2" innerThickness 2
extrude "Extrude91" cut sketch "Sketch68" profile of L8 C1 L10 L11 L12 L13 against normal blind 87
fillet "Fillet53" radius 2
fillet "Fillet66" radius 3
fillet "Fillet68" radius 2
extrude "Extrude95" cut of existing geometry blind -7
extrude "Extrude107" cut of existing geometry blind 39
extrude "Extrude108" cut of existing geometry blind -30
extrude "Extrude96" cut of existing geometry blind -7
sketch "Sketch78" plane through (0, -51.9991, 0) normal (0, -1, 0) x axis (1, 0, 0)
  line L1 (-29.1136, 27.1272) -> (-29.1136, 3.6857)
  arc A1 centre (-23.7386, 15.4065) radius 12.8944 clockwise from (-29.1136, 3.6857) to (-29.1136, 27.1272)
  circle C1 centre (-28.7111, 17.4065) radius 0.975
  circle C2 centre (-28.7111, 17.4065) radius 2
  concentric C1 C2
  dimension "d835" diameter C2 = 4
sketch "Sketch79" plane through (0, -27.9991, 0) normal (0, 1, 0) x axis (-1, 0, 0)
  curve K1 (29.1562, 16.539) -> (27.8436, 17.8516)
  line L1 (29.1136, 3.6857) -> (29.1136, 27.1272)
  arc A1 centre (23.7386, 15.4065) radius 12.8944 clockwise from (29.1136, 27.1272) to (29.1136, 3.6857)
  arc A2 centre (28.7111, 17.4065) radius 0.975 clockwise from (29.1562, 16.539) to (27.8436, 17.8516)
  circle C1 centre (28.7111, 17.4065) radius 2
  point P10 (28.7111, 17.4065)
  point P11 (28.7111, 17.4065)
  coincident P10 P11
  dimension "d834" diameter C1 = 4
extrude "Extrude97" cut sketch "Sketch65" along normal blind 11.5
extrude "Extrude104" cut sketch "Sketch78" profile of C1 C2 along normal blind 3.5
extrude "Extrude98" cut sketch "Sketch66" along normal blind 8.5
extrude "Extrude105" cut sketch "Sketch79" profile of K1 A2 C1 along normal blind 9
fillet "Fillet75" radius 0.5
fillet "Fillet76" radius 2
fillet "Fillet77" radius 1
fillet "Fillet78" radius 1
fillet "Fillet79" radius 3
fillet "Fillet80" radius 1
extrude "Extrude109" cut of existing geometry blind -3
extrude "Extrude110" cut of existing geometry blind -2
fillet "Fillet81" radius 3
fillet "Fillet82" radius 1.5
fillet "Fillet83" radius 1
fillet "Fillet84" radius 1
fillet "Fillet85" radius 1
